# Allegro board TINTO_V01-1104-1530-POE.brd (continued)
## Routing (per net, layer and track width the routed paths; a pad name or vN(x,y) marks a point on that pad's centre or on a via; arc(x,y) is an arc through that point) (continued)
N17701702: length 10.5
  TOP w0.381: v1(185.03,12.85) 185.03,11.78 LED38.4 ; v1(190,17.82) 191.11,17.82 LED36.3
  IN1 w0.381: v1(185.03,12.85) v1(190,17.82)
N17701704: length 16
  TOP w0.381: LED21.2 v1(12.14,124.69) ; LED23.1 v1(12.11,110.13)
  IN1 w0.381: v1(12.14,124.69) 12.14,110.17 v1(12.11,110.13)
N17701706: length 15.9
  TOP w0.381: v1(11.5,110.87) 10.97,110.87 10.63,110.53 LED23.3 ; LED21.4 10.63,124.21 10.98,123.86 v1(11.5,123.86)
  IN1 w0.381: v1(11.5,110.87) v1(11.5,123.86)
N17702195: length 10.5
  TOP w0.381: LED37.4 20.5,10.74 20.91,11.15 v1(20.91,11.58) ; v1(27.96,11.58) 27.96,10.83 28.16,10.64 LED39.3
  IN1 w0.381: v1(27.96,11.58) v1(20.91,11.58)
N17702197: length 10.4
  TOP w0.381: LED37.2 v1(19.86,12.24) ; LED39.1 28.67,12.12 v1(28.67,12.13)
  IN1 w0.381: v1(28.67,12.13) 28.55,12.24 v1(19.86,12.24)
N17702222: length 10.3
  TOP w0.381: v1(190.36,20.88) 191.37,19.87 ; LED34.1 v1(190.36,28.65)
  IN1 w0.381: v1(190.36,28.65) v1(190.36,20.88)
N17702224: length 10.3
  TOP w0.381: v1(191,27.78) 191.56,27.78 192.18,28.4 LED34.3 ; LED36.4 192.07,20.18 v1(191,21.25)
  IN1 w0.381: v1(191,21.25) v1(191,27.78)
N17702236: length 16.2
  TOP w0.381: v1(190.62,44.64) 190.63,44.65 LED32.1 ; v1(190.62,30.11) 190.63,30.1 LED34.2
  IN1 w0.381: v1(190.62,30.11) 190.61,30.12 190.61,44.64 v1(190.62,44.64)
N17702240: length 15.9
  TOP w0.381: v1(191.26,43.9) 191.77,43.9 192.18,44.3 LED32.3 ; LED34.4 192.18,30.4 191.78,30.79 v1(191.25,30.79)
  IN1 w0.381: v1(191.25,30.79) 191.25,43.88 v1(191.26,43.9)
N17702242: length 16.2
  TOP w0.381: LED32.2 190.78,46.1 190.55,46.33 v1(190.55,46.35) ; LED30.1 v1(190.53,60.65)
  IN1 w0.381: v1(190.53,60.65) 190.53,46.36 v1(190.55,46.35)
N17702244: length 16
  TOP w0.381: v1(191.17,59.87) 191.66,59.87 192.18,60.39 LED30.3 ; LED32.4 192.18,46.47 191.74,46.91 v1(191.17,46.91)
  IN1 w0.381: v1(191.17,46.91) v1(191.17,59.87)
N17702269: length 16.1
  TOP w0.381: v1(190.68,92.63) 190.69,92.63 LED26.1 ; LED28.2 v1(190.75,78.11)
  IN1 w0.381: v1(190.75,78.11) 190.5,78.35 190.5,92.45 v1(190.68,92.63)
N17702271: length 16.1
  TOP w0.381: v1(191.13,78.83) 191.68,78.83 192.18,78.33 LED28.4 ; v1(191.13,91.86) 191.75,91.86 192.15,92.26 LED26.3
  IN1 w0.381: v1(191.13,78.83) v1(191.13,91.86)
N17702317: length 16.3
  TOP w0.381: LED28.1 190.6,76.66 v1(190.59,76.67) ; v1(190.59,62.09) 190.6,62.1 LED30.2
  IN1 w0.381: v1(190.59,62.09) 190.59,62.09 v1(190.59,76.67)
N17702327: length 15.9
  TOP w0.381: LED30.4 192.18,62.47 191.82,62.83 v1(191.23,62.83) ; LED28.3 192.18,76.38 191.65,75.86 v1(191.23,75.86)
  IN1 w0.381: v1(191.23,62.83) v1(191.23,75.86)
N17702414: length 16.3
  TOP w0.381: v1(60.69,12.38) 60.68,12.37 LED41.1 ; v1(46.54,12.38) 46.13,11.96 LED40.2
  IN1 w0.381: v1(46.54,12.38) v1(60.69,12.38)
N17702416: length 16.1
  TOP w0.381: v1(59.91,11.69) 59.91,11.1 60.37,10.64 LED41.3 ; v1(46.85,11.62) 46.82,11.59 46.82,11.03 46.42,10.64 LED40.4
  IN1 w0.381: v1(59.91,11.69) 46.92,11.69 v1(46.85,11.62)
N17702418: length 16.1
  TOP w0.381: LED41.2 v1(62.13,12.1) ; LED42.1 v1(76.68,12.09)
  IN1 w0.381: v1(62.13,12.1) 62.3,12.27 76.5,12.27 v1(76.68,12.09)
N17702420: length 16
  TOP w0.381: v1(62.98,11.62) 62.98,11.62 62.98,11.21 62.4,10.64 LED41.4 ; v1(75.97,11.63) 75.95,11.61 75.95,11.02 76.33,10.64 LED42.3
  IN1 w0.381: v1(62.98,11.62) 62.99,11.63 v1(75.97,11.63)
N17702422: length 16.2
  TOP w0.381: LED42.2 v1(78.13,12.09) ; LED43.1 v1(92.68,12.09)
  IN1 w0.381: v1(78.13,12.09) 78.42,12.38 92.39,12.38 v1(92.68,12.09)
N17702424: length 16.2
  TOP w0.381: LED43.3 92.41,10.64 92.03,11.01 v1(92.03,11.73) ; v1(78.9,11.73) 78.9,11.14 78.4,10.64 LED42.4
  IN1 w0.381: v1(92.03,11.73) v1(78.9,11.73)
N17702426: length 16.4
  TOP w0.381: v1(110.14,12.32) 110.13,12.31 LED44.2 ; LED45.1 124.69,12.28 v1(124.69,12.29)
  IN1 w0.381: v1(110.14,12.32) 110.18,12.35 124.62,12.35 v1(124.69,12.29)
N17702428: length 16.2
  TOP w0.381: LED45.3 124.33,10.64 123.97,11 v1(123.97,11.69) ; LED44.4 110.45,10.64 110.82,11.01 v1(110.82,11.69)
  IN1 w0.381: v1(123.97,11.69) v1(110.82,11.69)
N17702430: length 16.3
  TOP w0.381: LED44.1 v1(108.68,12.19) ; LED43.2 v1(94.13,12.11)
  IN1 w0.381: v1(94.13,12.11) 94.4,12.38 108.49,12.38 v1(108.68,12.19)
N17702432: length 16.2
  TOP w0.381: LED43.4 94.52,10.64 95.09,11.21 v1(95.09,11.74) ; LED44.3 108.23,10.64 107.88,10.99 v1(107.88,11.74)
  IN1 w0.381: v1(107.88,11.74) v1(95.09,11.74)
N17702434: length 16.3
  TOP w0.381: LED46.1 140.69,12.25 v1(140.66,12.28) ; v1(126.14,12.27) LED45.2
  IN1 w0.381: v1(140.66,12.28) 126.14,12.28 v1(126.14,12.27)
N17702436: length 16
  TOP w0.381: LED45.4 126.42,10.64 126.96,11.18 v1(126.96,11.64) ; LED46.3 140.46,10.64 139.99,11.11 v1(139.99,11.64)
  IN1 w0.381: v1(139.99,11.64) v1(126.96,11.64)
N17702438: length 16
  TOP w0.381: LED47.1 v1(156.69,12.11) ; LED46.2 v1(142.14,12.09)
  IN1 w0.381: v1(156.69,12.11) 156.66,12.14 142.19,12.14 v1(142.14,12.09)
N17702440: length 15.8
  TOP w0.381: LED47.3 156.44,10.64 155.94,11.13 v1(155.94,11.51) ; v1(142.9,11.51) 142.9,11.04 142.49,10.64 LED46.4
  IN1 w0.381: v1(155.94,11.51) v1(142.9,11.51)
N17702495: length 10.2
  TOP w0.381: v1(20.08,190.61) 20.08,191.22 LED11.1 ; LED1.2 v1(28.67,190.61)
  IN1 w0.381: v1(20.08,190.61) v1(28.67,190.61)
N17702497: length 10.2
  TOP w0.381: LED1.4 28.29,192.16 27.94,191.8 v1(27.94,191.26) ; v1(20.79,191.26) 20.79,191.57 20.29,192.08 LED11.3
  IN1 w0.381: v1(27.94,191.26) v1(20.79,191.26)
N17702499: length 9.8
  TOP w0.381: LED11.2 18.57,190 v1(18.28,189.71) ; v1(12.82,184.27) LED13.1
  IN1 w0.381: v1(18.28,189.71) 12.84,184.27 v1(12.82,184.27)
N17702501: length 10.5
  TOP w0.381: LED11.4 17.79,191.04 v1(17.79,190.17) ; v1(12.64,185.02) 11.73,185.02 LED13.3
  IN1 w0.381: v1(12.64,185.02) v1(17.79,190.17)
N17702503: length 9.6
  TOP w0.381: LED13.2 v1(12.14,182.19) ; LED15.1 11.76,174.14 v1(12.11,174.49)
  IN1 w0.381: v1(12.14,182.19) 12.16,182.17 12.16,174.55 v1(12.11,174.49)
N17702505: length 10.2
  TOP w0.381: LED15.3 10.63,174.47 11.1,174.94 v1(11.48,174.94) ; LED13.4 10.72,182.33 11.09,181.96 v1(11.53,181.96)
  IN1 w0.381: v1(11.53,181.96) 11.53,174.99 v1(11.48,174.94)
N17702507: length 16
  TOP w0.381: LED17.2 v1(12.14,156.69) ; LED19.1 v1(12.08,142.14)
  IN1 w0.381: v1(12.14,156.69) 12.14,142.2 v1(12.08,142.14)
N17702509: length 15.8
  TOP w0.381: LED17.4 10.63,156.23 10.9,155.96 v1(11.47,155.96) ; LED19.3 10.63,142.41 11.11,142.89 v1(11.47,142.89)
  IN1 w0.381: v1(11.47,142.89) v1(11.47,155.96)
N17702511: length 16
  TOP w0.381: LED15.2 v1(12.12,172.69) ; LED17.1 v1(12.08,158.14)
  IN1 w0.381: v1(12.12,172.69) 12.11,172.68 12.11,158.17 v1(12.08,158.14)
N17702513: length 15.8
  TOP w0.381: v1(11.48,158.91) 11.08,158.91 10.63,158.46 LED17.3 ; v1(11.48,171.86) 11.02,171.86 10.63,172.24 LED15.4
  IN1 w0.381: v1(11.48,158.91) v1(11.48,171.86)
N17702515: length 16.1
  TOP w0.381: LED21.1 v1(12.1,126.14) ; LED19.2 v1(12.11,140.69)
  IN1 w0.381: v1(12.11,140.69) 12.18,140.62 12.18,126.22 v1(12.1,126.14)
N17702517: length 15.9
  TOP w0.381: v1(11.51,139.98) 10.92,139.98 10.63,140.27 LED19.4 ; LED21.3 10.63,126.53 11.02,126.92 v1(11.51,126.92)
  IN1 w0.381: v1(11.51,126.92) v1(11.51,139.98)
N17702581: length 10.4
  TOP w0.381: LED48.2 v1(174.14,12.29) ; LED38.1 182.68,11.62 v1(182.68,12.3)
  IN1 w0.381: v1(182.68,12.3) 182.67,12.29 v1(174.14,12.29)
N17702583: length 10.5
  TOP w0.381: v1(182.03,11.63) 182.03,11.2 182.51,10.72 183.17,10.72 ; LED48.4 174.49,10.64 175.03,11.18 v1(175.03,11.72)
  IN1 w0.381: v1(175.03,11.72) 175.11,11.63 v1(182.03,11.63)
N17736265: length 16
  TOP w0.381: v1(190.7,110.08) 190.71,110.08 LED24.2 ; LED22.1 v1(190.74,124.64)
  IN1 w0.381: v1(190.74,124.64) 190.68,124.58 190.68,110.11 v1(190.7,110.08)
N17736966: length 15.9
  TOP w0.381: v1(191.31,123.93) 191.91,123.93 192.18,124.2 LED22.3 ; LED24.4 192.18,110.4 191.76,110.82 v1(191.31,110.82)
  IN1 w0.381: v1(191.31,123.93) v1(191.31,110.82)
N17737669: length 16
  TOP w0.381: v1(190.7,126.09) 190.71,126.09 LED22.2 ; LED20.1 v1(190.72,140.64)
  IN1 w0.381: v1(190.72,140.64) 190.67,140.59 190.67,126.13 v1(190.7,126.09)
N17738374: length 15.8
  TOP w0.381: v1(191.3,126.97) 191.55,126.97 192.18,126.34 LED22.4 ; LED20.3 192.18,140.11 191.88,139.81 v1(191.3,139.81)
  IN1 w0.381: v1(191.3,126.97) v1(191.3,139.81)
N17739081: length 16
  TOP w0.381: LED20.2 v1(190.73,142.09) ; LED18.1 v1(190.73,156.67)
  IN1 w0.381: v1(190.73,142.09) 190.68,142.13 190.68,156.63 v1(190.73,156.67)
N17739790: length 15.9
  TOP w0.381: LED20.4 192.18,142.51 191.83,142.87 v1(191.32,142.87) ; LED18.3 192.18,156.15 191.86,155.83 v1(191.32,155.83)
  IN1 w0.381: v1(191.32,155.83) v1(191.32,142.87)
N17740501: length 16.1
  TOP w0.381: LED16.1 v1(190.74,172.64) ; LED18.2 v1(190.75,158.12)
  IN1 w0.381: v1(190.74,172.64) 190.56,172.46 190.56,158.3 v1(190.75,158.12)
N17741214: length 16
  TOP w0.381: v1(191.2,171.92) 191.76,171.92 192.18,172.34 LED16.3 ; v1(191.2,158.97) 191.7,158.97 192.18,158.48 LED18.4
  IN1 w0.381: v1(191.2,171.92) v1(191.2,158.97)
N17741929: length 10.1
  TOP w0.381: LED16.2 190.65,174.09 v1(190.65,174.09) ; LED14.1 191.01,182.88 v1(190.62,182.49)
  IN1 w0.381: v1(190.65,174.09) 190.62,174.11 v1(190.62,182.49)
N17742646: length 10.4
  TOP w0.381: LED14.3 192.08,182.39 191.73,182.05 v1(191.27,182.05) ; LED16.4 192.18,174.57 191.88,174.87 191.27,174.87 v1(191.27,174.87)
  IN1 w0.381: v1(191.27,174.87) v1(191.27,182.05)
N17743365: length 9.8
  TOP w0.381: LED14.2 190.01,184.23 v1(190,184.24) ; LED12.1 v1(184.28,189.92)
  IN1 w0.381: v1(184.28,189.92) 184.31,189.92 v1(190,184.24)
N17744086: length 10.5
  TOP w0.381: LED12.3 184.97,191.1 v1(184.97,190.18) ; v1(190.23,184.94) 191.12,184.94 LED14.4
  IN1 w0.381: v1(190.23,184.94) 184.99,190.18 v1(184.97,190.18)
N17744809: length 9.8
  TOP w0.381: v1(182.15,190.57) 182.15,190.57 LED12.2 ; v1(174.46,190.57) 174.12,190.92 LED10.1
  IN1 w0.381: v1(174.46,190.57) 182.15,190.57 v1(182.15,190.57)
N17745534: length 10.1
  TOP w0.381: v1(174.95,191.24) 174.95,191.85 174.65,192.16 LED10.3 ; LED12.4 182.65,192.04 v1(181.86,191.24)
  IN1 w0.381: v1(181.86,191.24) 174.95,191.24 v1(174.95,191.24)
N17756919: length 16
  TOP w0.381: LED9.2 v1(156.66,190.7) ; LED8.1 142.11,190.72 v1(142.12,190.71)
  IN1 w0.381: v1(156.66,190.7) 156.63,190.66 142.17,190.66 v1(142.12,190.71)
N17756921: length 15.8
  TOP w0.381: LED9.4 156.26,192.16 155.87,191.76 v1(155.87,191.3) ; LED8.3 142.38,192.16 142.85,191.7 v1(142.85,191.3)
  IN1 w0.381: v1(142.85,191.3) v1(155.87,191.3)
N17756923: length 16
  TOP w0.381: v1(126.12,190.71) 126.11,190.72 LED7.1 ; LED8.2 v1(140.66,190.68)
  IN1 w0.381: v1(126.12,190.71) 126.15,190.68 140.66,190.68 v1(140.66,190.68)
N17756925: length 15.7
  TOP w0.381: LED7.3 126.45,192.16 126.82,191.79 v1(126.82,191.32) ; LED8.4 140.34,192.16 139.88,191.7 v1(139.88,191.32)
  IN1 w0.381: v1(126.82,191.32) v1(139.88,191.32)
N17756927: length 15.9
  TOP w0.381: LED6.1 110.13,190.72 v1(110.14,190.71) ; LED7.2 v1(124.66,190.72)
  IN1 w0.381: v1(110.14,190.71) 110.17,190.69 124.63,190.69 v1(124.66,190.72)
N17756929: length 15.8
  TOP w0.381: LED6.3 110.6,192.16 110.91,191.86 v1(110.91,191.32) ; LED7.4 124.29,192.16 123.9,191.77 v1(123.9,191.32)
  IN1 w0.381: v1(110.91,191.32) v1(123.9,191.32)
N17756931: length 16
  TOP w0.381: v1(108.67,190.71) 108.68,190.73 LED6.2 ; LED5.1 v1(94.13,190.71)
  IN1 w0.381: v1(94.13,190.71) 94.16,190.68 108.64,190.68 v1(108.67,190.71)
N17756933: length 15.8
  TOP w0.381: LED6.4 108.31,192.16 107.92,191.76 v1(107.92,191.31) ; LED5.3 94.51,192.16 94.87,191.79 v1(94.87,191.31)
  IN1 w0.381: v1(94.87,191.31) v1(107.92,191.31)
N17756935: length 16
  TOP w0.381: LED5.2 v1(92.68,190.72) ; LED4.1 v1(78.13,190.69)
  IN1 w0.381: v1(78.13,190.69) 92.64,190.69 v1(92.68,190.72)
N17756937: length 15.6
  TOP w0.381: v1(91.93,191.32) 91.93,191.63 92.45,192.16 LED5.4 ; LED4.3 78.4,192.16 78.9,191.65 v1(78.9,191.32)
  IN1 w0.381: v1(91.93,191.32) v1(78.9,191.32)
N17756939: length 16
  TOP w0.381: LED3.1 v1(62.13,190.71) ; LED4.2 v1(76.68,190.73)
  IN1 w0.381: v1(62.13,190.71) 62.21,190.63 76.58,190.63 v1(76.68,190.73)
N17756941: length 15.7
  TOP w0.381: LED3.3 62.39,192.16 62.86,191.69 v1(62.86,191.3) ; LED4.4 76.38,192.16 75.9,191.67 v1(75.9,191.3)
  IN1 w0.381: v1(75.9,191.3) v1(62.86,191.3)
N17756943: length 15.9
  TOP w0.381: v1(46.36,190.68) 46.13,190.92 LED2.1 ; LED3.2 v1(60.68,190.67)
  IN1 w0.381: v1(46.36,190.68) 46.39,190.65 60.66,190.65 v1(60.68,190.67)
N17756945: length 15.8
  TOP w0.381: LED2.3 46.47,192.16 46.89,191.74 v1(46.89,191.29) ; LED3.4 60.31,192.16 59.9,191.75 v1(59.9,191.29)
  IN1 w0.381: v1(46.89,191.29) v1(59.9,191.29)
N25585706: length 19.3
  BOTTOM w0.254: C264.2 C276.2 43.65,134.76 42.3,133.41 42.3,132.47 43.44,131.34 43.69,131.34 U25.4 44.85,127.5 45.98,126.37 48.62,126.37 49.26,127.02 49.26,127.26 R219.1 R216.2
N25585768: length 4.9
  BOTTOM w0.508: T1.1 67.99,144.77 R193.2
N25585770: length 8.9
  BOTTOM w0.254: D12.P 46,132.71 45.73,132.98 U25.3 44.85,133.64 45.53,134.32 C276.1 45.53,135.36 45.45,135.43 R208.1 46.58,136.13 47.33,136.88 U22.2
N25585804: length 30
  TOP w0.381: U4.4 v1(86.85,147.3)
  IN2 w0.508: v1(86.85,147.3) 81.77,147.3 77.58,143.11 77.58,137.52 75.23,135.17 v1(73.01,135.17)
  BOTTOM w0.508: D10.3 69.71,136.03 C275.1 69.74,135.05 70.01,135.05 C278.1 72.88,135.05 v1(73.01,135.17)
N25586716: length 14.9
  BOTTOM w0.254: R216.1 50.51,132.01 49.81,132.71 D12.N 48.92,127.89 48.01,126.98 R236.1 ; R217.2 51.78,132.04 49.26,134.55 R213.1
  BOTTOM w0.508: R216.1 R217.2
N25586736: length 4.8
  BOTTOM w0.508: R193.1 71.55,142.24 71.08,141.77 C259.1 71.08,140.65 D10.1
N25586772: length 2.6
  TOP w0.305: R48.1 88.88,141.59 88.15,142.32 U4.13
N25586778: length 2.7
  TOP w0.305: U4.14 88.9,142.2 89.87,141.23 R49.1
N25586811: length 1.8
  BOTTOM w0.508: U22.1 R213.2
N25586821: length 4.1
  TOP w0.381: U4.3 87.5,151.38 R11.2
N25586908: length 23.5
  TOP w0.508: Q1.4 62.82,155.05 83.91,155.05 R16.2
N25586910: length 25.2
  TOP w0.508: R11.1 v1(85.84,155.56)
  IN1 w0.508: v1(85.84,155.56) 83.42,153.15 65.01,153.15 v1(63.36,151.49)
N25587094: length 3
  TOP w0.305: U4.10 86.2,142.46 84.95,141.21 R54.2
N25587194: length 1.4
  BOTTOM w0.254: R208.2 C264.1
N25587240: length 4.7
  BOTTOM w0.254: C283.1 46.54,129.99 47.26,130.71 D12.NP
  BOTTOM w0.508: R236.2 C283.1
N25587378: length 2.6
  TOP w0.305: U4.11 86.85,142.27 86.34,141.77 R55.2
N25587545: length 4.2
  TOP w0.381: U4.5 86.2,151.28 R16.1
N25594365: length 13.9
  TOP w0.102: CN3.5 80.26,111.19 CN3.6 83.73,114.66 88.02,114.66 C153.2
N25594481: length 12.7
  TOP w0.102: CN3.12 81.64,117.2 82.91,118.47 87.36,118.47 89.14,120.25 R97.1
N25594574: length 6.4
  TOP w0.102: R98.1 88.88,119.24 87.87,118.22 84.84,118.22 CN3.13
N25594579: length 5.8
  TOP w0.102: R99.1 91.4,119.08 89.52,117.2 CN3.14
N26013479: length 1.4
  TOP w0.381: R10.1 88.66,155.29 88.63,155.27 C28.2

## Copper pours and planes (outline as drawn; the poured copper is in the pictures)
3VDDM on BOTTOM (solid shape): 142.99,166.99 142.99,165.48 142.78,165.28 142.51,165.28 142.22,165.22 141.97,165.05 141.93,165.02 139.26,165.02 138.44,164.19 137.14,164.19 136.93,164.41 136.93,166.01 137.27,166.35 137.65,166.35 137.91,166.61 137.91,167.24 138.03,167.37 142.6,167.37
5V_SW on BOTTOM (solid shape): 36,119.45 36,118.12 38.32,115.8 38.32,110.67 37.5,109.85 33.86,109.85 33.51,110.2 33.51,114.46 34.35,115.3 34.35,116.91 34.95,117.51 34.95,119.57 35.13,119.75 35.7,119.75
5VDDM on BOTTOM (solid shape): 37.38,90.02 37.38,87.52 36.46,86.6 33.98,86.6 33.17,87.41 33.17,90.12 33.62,90.57 36.83,90.57
5VDDM on BOTTOM (solid shape): 120.89,94.22 120.89,92.82 120.63,92.57 118.86,92.57 118.47,92.95 118.47,94.47 118.73,94.73 120.38,94.73
5VDDM on BOTTOM (solid shape): 143.68,44.85 143.68,42.9 143.47,42.7 140.67,42.7 140.61,42.76 140.61,44.74 141.16,45.29 143.23,45.29
5VDDM on BOTTOM (solid shape): 112.18,92.26 112.18,90.32 112.16,90.29 112.16,89.68 112.02,89.54 110.5,89.54 110.37,89.67 110.37,92.21 110.48,92.32 112.13,92.32
5VDDM on BOTTOM (solid shape): 98.36,179.39 98.43,179.33 98.69,179.08 99.7,179.08 100.21,178.57 100.21,175.9 100.08,175.78 97.67,175.78 96.91,176.54 96.91,179.2 97.16,179.46 98.31,179.46
5VDDM on BOTTOM (solid shape): 170.12,72.33 170.12,71.22 170.12,71.21 170.12,68.3 170.39,68.03 170.39,67.82 170.39,67.82 170.39,67.3 170.38,67.3 170.38,67.11 169.77,66.5 169.77,65.59 169.57,65.39 167.99,65.39 167.76,65.62 167.76,69.47 168.11,69.83 168.11,69.99 168.11,70 168.13,70.11 168.11,70.22 168.11,70.23 168.11,70.46 167.79,70.78 166.09,70.78 165.89,70.58 165.89,68.85 165.81,68.59 165.89,68.33 165.89,67.65 165.81,67.57 165.81,67.01 165.2,66.39 165.2,65.57 164.9,65.28 163.44,65.28 162.91,65.81 162.91,71.42 164.31,72.83 169.63,72.83
5VDDM on VCC2 (solid shape): outline of 638 points within 29.19,42.91 171.94,192.29
5VDDM_VIN on BOTTOM (solid shape): 32.75,119.74 33,119.74 33.26,119.49 33.26,118.09 29.32,114.16 27.29,114.16 26.78,114.66 26.78,120.47 27.07,120.76 31.73,120.76
DVDDL_RGMII on BOTTOM (solid shape): 109.28,121.33 109.28,120.26 109.3,120.13 109.35,120.01 109.36,120 109.36,119.8 108.75,119.19 108.75,118.4 109.2,117.95 109.2,116.34 109.51,116.03 109.51,114.88 108.31,113.69 107.14,113.69 107.04,113.78 107.04,116.13 107.18,116.26 107.58,116.45 107.64,116.9 107.76,117.21 107.6,117.61 107.63,117.69 107.76,118.04 107.59,118.37 107.54,118.45 107.57,118.55 107.66,118.94 107.41,119.25 107.41,119.39 107.4,119.4 107.4,119.57 107.65,119.82 108.46,119.82 108.8,120.16 108.8,121.29 108.89,121.38 109.23,121.38
GND on TOP (solid shape): 11.02,155.41 11.02,143.4 11,143.38 10.53,143.38 10.51,143.4 10.51,155.4 10.55,155.44 10.98,155.44
GND on TOP (solid shape): 11.02,75.33 11.02,63.54 11,63.52 10.53,63.52 10.51,63.54 10.51,75.32 10.55,75.36 10.98,75.36
GND on TOP (solid shape): 11.02,59.23 11.02,47.62 10.98,47.58 10.54,47.58 10.51,47.62 10.51,59.24 10.54,59.27 10.98,59.27
GND on TOP (solid shape): 52.05,139.43 52.05,137.14 51.42,136.51 47.61,136.51 47.23,136.89 47.23,139.43 47.74,139.94 51.55,139.94
GND on TOP (solid shape): 11.02,171.33 11.02,159.43 11,159.41 10.52,159.41 10.51,159.43 10.51,171.35 10.52,171.36 10.98,171.36
GND on TOP (solid shape): 11.02,139.45 11.02,127.46 10.98,127.43 10.54,127.43 10.51,127.47 10.51,139.47 10.52,139.49 10.98,139.49
GND on TOP (solid shape): 11.02,123.33 11.02,111.39 10.99,111.36 10.53,111.36 10.51,111.38 10.51,123.34 10.53,123.36 10.98,123.36
GND on TOP (solid shape): 11.02,107.5 11.02,95.64 10.99,95.61 10.54,95.61 10.51,95.65 10.51,107.51 10.53,107.54 10.98,107.54
GND on TOP (solid shape): 11.02,91.37 11.02,79.51 10.86,79.36 10.57,79.36 10.51,79.42 10.51,91.37 10.53,91.39 10.99,91.39
GND on TOP (solid shape): 192.29,155.32 192.29,143.39 192.27,143.36 191.82,143.36 191.78,143.4 191.78,155.28 191.84,155.33 192.27,155.33
GND on TOP (solid shape): 192.29,139.3 192.29,127.29 192.25,127.25 191.97,127.25 191.78,127.43 191.78,139.27 191.84,139.32 192.28,139.32
GND on TOP (solid shape): 192.29,171.4 192.29,159.38 192.27,159.36 192.01,159.36 191.9,159.46 191.83,159.46 191.78,159.51 191.78,171.39 191.82,171.43 192.26,171.43
GND on TOP (solid shape): 192.29,123.4 192.29,111.27 192.26,111.24 192.05,111.24 191.97,111.32 191.83,111.32 191.78,111.36 191.78,123.38 191.84,123.43 192.26,123.43
GND on TOP (solid shape): outline of 183 points within 24.62,101.33 40.24,129.27
GND on TOP (solid shape): outline of 478 points within 41.51,92.31 71.99,130.67
GND on TOP (solid shape): outline of 136 points within 10.51,175.45 44.62,192.29
GND on BOTTOM (solid shape): 27.11,50.16 27.11,48.06 27.06,48.01 24.98,48.01 24.94,48.05 24.94,50.45 25,50.51 26.76,50.51
GND on BOTTOM (solid shape): 105.37,122.18 105.37,118.72 105.2,118.55 101.5,118.55 101.31,118.74 101.31,122.19 101.52,122.4 105.15,122.4
GND on BOTTOM (solid shape): 122.82,112.36 122.82,111.16 122.7,111.05 120.75,111.05 120.63,111.16 120.63,112.29 120.8,112.46 122.72,112.46
GND on BOTTOM (solid shape): 114.51,162.94 114.51,161.5 114.44,161.43 111.22,161.43 111.22,162.8 111.55,163.13 114.33,163.13
GND on BOTTOM (solid shape): 32.06,47.71 32.06,46.92 31.89,46.75 30.62,46.75 30.44,46.92 30.44,47.58 30.67,47.82 30.99,47.82 31,47.84 31.94,47.84
GND on BOTTOM (solid shape): 43.04,172.7 43.04,169.54 42.97,169.48 41.69,169.48 41.64,169.53 41.64,170.8 40.81,171.62 40.81,172.56 41.05,172.79 42.95,172.79
GND on BOTTOM (solid shape): 52.43,185.02 52.43,183.37 52.31,183.24 51.55,183.24 51.42,183.37 51.42,185.02 51.55,185.15 52.31,185.15
GND on BOTTOM (solid shape): 98.93,78.9 98.93,78.37 99.45,77.85 99.45,76.02 99.21,75.78 96.84,75.78 96.61,76 96.61,79.17 96.8,79.35 98.47,79.35
GND on BOTTOM (solid shape): 104.6,78.71 104.6,77.57 104.5,77.47 102.81,77.47 102.67,77.62 102.67,78.68 102.78,78.79 104.52,78.79
GND on BOTTOM (solid shape): 108.37,160.88 108.37,159.15 108.25,159.02 104.89,159.02 104.77,159.15 104.77,162.19 105.01,162.43 106.82,162.43
GND on BOTTOM (solid shape): 129.8,167.06 129.8,166.38 129.7,166.28 129.29,166.28 128.86,165.84 125.15,165.84 124.94,166.06 124.94,167.28 125.03,167.37 129.5,167.37
GND on BOTTOM (solid shape): 131.88,163.96 132.75,163.96 132.98,163.74 132.98,162.95 132.77,162.75 130,162.75 129.83,162.92 129.83,163.71 130.11,163.99 131.85,163.99
GND on BOTTOM (solid shape): 145.02,160.77 145.02,158.71 144.81,158.5 139.4,158.5 139.23,158.68 139.23,160.92 139.39,161.08 144.7,161.08
GND on BOTTOM (solid shape): 61.07,172.57 61.07,169.53 60.94,169.4 59.93,169.4 59.67,169.66 59.67,170.67 59.17,171.18 58.66,171.18 58.4,171.43 58.4,173.18 58.68,173.46 60.18,173.46
GND on BOTTOM (solid shape): 62.98,184.13 62.98,180.59 62.72,180.34 61.83,180.34 61.32,180.85 61.32,182.99 61.71,183.37 61.71,184.13 61.83,184.26 62.85,184.26
GND on BOTTOM (solid shape): 111.01,133.84 111.01,132.98 111.39,132.6 111.39,132.06 111.26,131.94 110.98,131.94 110.65,132.27 110.19,132.27 109.86,132.6 109.86,133.69 110.27,134.1 110.75,134.1
GND on BOTTOM (solid shape): 114.66,167.24 114.66,163.94 114.62,163.89 112.84,163.89 112.63,164.1 112.63,167.15 112.8,167.33 114.58,167.33
GND on BOTTOM (solid shape): 126.33,111.51 127.53,111.51 127.67,111.37 127.67,110.96 127.54,110.83 124.5,110.83 124.33,111.01 124.33,111.55 124.47,111.69 124.99,111.69 125,111.7 126.15,111.7
GND on BOTTOM (solid shape): 137.65,167.32 137.65,166.73 137.52,166.61 137.22,166.61 136.92,166.3 136.53,166.3 136.46,166.38 136.46,167.32 136.53,167.4 137.58,167.4
GND on BOTTOM (solid shape): 71.1,126.98 71.1,114.92 70.6,114.41 68.06,114.41 67.55,114.92 67.55,120.51 68.94,121.9 68.94,126.98 69.07,127.11 70.98,127.11
GND on BOTTOM (solid shape): 119.53,112.12 119.53,111.67 119.37,111.5 119.37,110.91 119.22,110.76 118.22,110.76 118.01,110.97 116.82,110.97 116.78,111.01 116.78,112.04 117.04,112.3 119.35,112.3
GND on BOTTOM (solid shape): 44.69,184.01 44.69,183.23 44.94,182.99 44.94,182.98 45.07,182.84 45.07,180.74 44.94,180.62 43.51,180.62 43.42,180.7 43.42,182.85 43.42,182.86 43.42,184.01 43.67,184.26 44.43,184.26
GND on BOTTOM (solid shape): 96.6,69.55 96.6,68.84 96.71,68.72 97.12,68.72 97.35,68.5 97.35,67 97.3,66.95 96.75,66.95 96.15,67.55 95.4,67.55 95.29,67.66 95.29,69.51 95.43,69.65 96.5,69.65
GND on BOTTOM (solid shape): 105.14,48.88 105.14,35.29 104.12,34.27 103.17,34.27 103.12,34.33 100.14,34.33 98.97,35.5 98.97,45.28 98.92,45.33 98.92,46.21 97.01,48.12 97.01,49.01 97.39,49.39 104.63,49.39
GND on BOTTOM (solid shape): 121.97,146.27 122.1,146.27 123,145.37 123,144.86 122.93,144.79 120.78,144.79 120.73,144.84 120.73,145.25 120.73,145.25 120.73,146.11 120.73,146.11 120.89,146.27 121.97,146.27
GND on BOTTOM (solid shape): 135.09,112.87 135.55,112.87 135.65,112.77 135.65,111.86 135.49,111.7 133.66,111.7 133.63,111.73 133.6,111.75 133.6,112.7 133.78,112.88 134.2,112.88 134.33,113 134.95,113
GND on BOTTOM (solid shape): 103.74,113.5 103.74,112.38 103.59,112.22 102.63,112.22 102.35,111.94 102.35,110.98 102.22,110.85 99.93,110.85 99.68,111.11 99.68,112.25 99.81,112.38 101.69,112.38 101.81,112.51 101.81,113.12 102.26,113.56 103.68,113.56
GND on BOTTOM (solid shape): 22.93,50.11 22.93,49.67 22.86,49.61 22.44,49.61 22.36,49.53 22.36,48.78 22.26,48.68 21.48,48.68 21.36,48.8 21.36,49.16 21.43,49.24 21.55,49.24 21.6,49.29 21.6,49.76 21.99,50.15 22.89,50.15
GND on BOTTOM (solid shape): 103.04,33.48 103.04,31.56 103.28,31.32 103.93,31.32 104.04,31.21 104.04,30.67 103.93,30.56 103.29,30.56 102.97,30.23 102.97,28.8 102.73,28.56 100.69,28.56 100.49,28.76 100.49,33.6 100.63,33.73 102.79,33.73
GND on BOTTOM (solid shape): 146.28,123.94 146.29,123.93 146.38,123.8 146.51,123.71 146.53,123.69 146.53,122.07 146.34,121.88 144.94,121.88 144.63,122.19 144.63,122.9 144.61,122.91 144.61,123.43 144.84,123.66 144.91,123.66 145.29,124.04 146.18,124.04
GND on BOTTOM (solid shape): 66.66,112.76 66.66,106.54 64.63,104.5 64.63,97.39 64.12,96.88 53.7,96.88 53.07,97.52 53.07,110.22 53.32,110.47 54.85,110.47 55.36,109.97 55.36,102.09 56.88,100.57 61.07,100.57 62.34,101.84 62.34,108.06 62.47,108.19 64.12,108.19 64.5,108.57 64.5,113.01 64.75,113.27 66.15,113.27
GND on BOTTOM (solid shape): 100.02,127.99 100.13,127.98 100.25,127.99 100.26,127.99 102.13,127.99 102.33,127.79 102.33,127.66 102.36,127.64 102.36,127.43 102.46,127.43 102.46,126.84 102.37,126.75 99.17,126.75 99.11,126.81 99.11,127.37 99.09,127.37 99.09,127.86 99.23,127.99 100.01,127.99
GND on BOTTOM (solid shape): 159.34,152.31 159.34,151.06 158.96,150.68 157.98,150.68 157.98,150.68 156.85,150.68 156.22,151.32 155.01,151.32 154.95,151.31 154.39,150.75 153.81,150.75 153.81,150.75 151.69,150.75 151.59,150.66 147.56,150.66 147.4,150.81 147.4,152.74 147.68,153.02 158.63,153.02
GND on BOTTOM (solid shape): 54.72,126.09 54.72,123.94 54.47,123.68 53.32,123.68 52.18,122.54 49.89,122.54 45.32,117.97 45.32,110.6 44.56,109.84 42.91,109.84 42.66,109.58 42.66,107.3 42.53,107.17 41.64,107.17 41.39,107.43 41.39,122.03 44.56,125.21 50.53,125.21 52.31,126.98 53.83,126.98
GND on BOTTOM (solid shape): 113.34,83.83 113.34,81.96 113.56,81.74 114.54,81.74 114.64,81.64 114.64,80.75 114.53,80.64 113.45,80.64 113.34,80.52 113.34,79.25 112.89,78.81 109.86,78.81 109.06,79.61 109.06,81.8 108.97,81.89 107.82,81.89 107.75,81.97 107.75,82.25 107.87,82.37 108.91,82.37 109.06,82.52 109.06,83.95 109.57,84.46 112.7,84.46
GND on BOTTOM (solid shape): 33.35,123.08 33.37,123.1 37.31,123.1 37.91,122.49 37.91,119 37.21,118.3 36.6,118.3 36.31,118.59 36.31,119.97 36.04,120.24 32.56,120.24 31.79,121.01 27.03,121.01 26.53,120.51 26.53,115.93 26.4,115.81 24.88,115.81 24.37,116.32 24.37,122.16 25.64,123.43 33,123.43
GND on BOTTOM (solid shape): 106.75,127.95 106.75,127.73 106.68,127.67 106.28,127.67 105.98,127.37 105.59,127.37 105.54,127.32 105.54,126.85 105.46,126.77 103.81,126.77 103.74,126.7 103.3,126.7 103.28,126.72 103.28,127.18 103.34,127.24 103.57,127.24 103.66,127.33 103.75,127.33 103.75,127.34 103.82,127.4 104.38,127.4 104.69,127.71 104.69,127.98 105.08,128.37 106.32,128.37
GND on BOTTOM (solid shape): 118.24,94.11 118.24,92.53 115.89,92.53 115.45,92.97 115.45,93.35 115.32,93.48 114.49,93.48 114.04,93.03 113.46,93.03 113.27,92.83 113.27,91.37 113.34,91.3 113.34,91.25 113.85,90.74 113.85,89.62 113.72,89.49 112.45,89.49 112.36,89.58 112.36,90.21 112.39,90.23 112.39,92.34 112.36,92.37 112.36,94.58 112.53,94.75 117.61,94.75
GND on BOTTOM (solid shape): 130.18,122.03 130.27,121.99 130.31,121.9 130.31,120.29 129.76,119.74 129.76,119.51 129.69,119.39 129.55,119.42 129.51,119.46 129.51,121.46 130.09,122.04
GND on BOTTOM (solid shape): 142.73,154.16 142.73,152 142.49,151.76 142.11,151.76 141.74,152.05 141.31,151.87 140.33,151.87 139.68,152.51 139.68,153.53 140.5,154.34 142.55,154.34
GND on BOTTOM (solid shape): 111.59,154.44 111.59,153.78 111.48,153.67 106.92,153.67 106.72,153.87 106.72,154.67 106.78,154.77 106.9,154.78 107.24,154.78 107.5,155.01 111.02,155.01
GND on BOTTOM (solid shape): 57.72,178.46 57.72,177.85 57.87,177.7 58.53,177.7 58.66,177.57 58.66,175.92 58.94,175.64 59.63,175.64 59.9,175.37 59.9,175.02 59.68,174.79 58.6,174.79 58.56,174.84 58.47,174.91 58.37,174.95 58.37,175.52 57.98,175.92 56.88,175.92 56.81,175.99 56.81,177.52 56.96,177.67 57.11,177.67 57.34,177.9 57.34,178.48 57.4,178.55 57.63,178.55
GND on BOTTOM (solid shape): 39.59,178.51 39.59,177.75 39.75,177.58 40.56,177.58 40.63,177.52 40.63,175.92 40.93,175.61 41.54,175.61 41.98,175.18 41.98,174.98 41.87,174.88 40.45,174.88 40.3,175.03 40.3,175.54 39.94,175.89 38.88,175.89 38.8,175.97 38.8,177.54 38.84,177.58 39.21,177.58 39.33,177.71 39.33,178.09 39.34,178.1 39.36,178.23 39.34,178.36 39.33,178.37 39.33,178.51 39.38,178.56 39.54,178.56
GND on BOTTOM (solid shape): 130.32,112.91 130.71,112.91 130.72,112.9 131.24,112.9 131.32,112.81 131.32,112.42 130.89,111.99 130.74,111.83 130.68,111.63 130.68,111.6 130.53,111.46 129.34,111.46 129.26,111.49 129.18,111.51 128.96,111.73 128.96,112.21 129.25,112.5 129.25,112.79 129.33,112.87 129.45,112.87 129.46,112.87 129.91,112.87 130.05,113.02 130.2,113.02
GND on BOTTOM (solid shape): 100.16,116.12 100.2,116.12 100.4,116.12 100.4,115.51 99.74,114.84 99.24,114.84 99.12,114.92 99.14,115.05 99.22,115.18 99.25,115.31 99.26,115.37 99.47,115.37 99.98,115.87 99.98,116 100.02,116.1 100.13,116.13
GND on BOTTOM (solid shape): 115.81,135.81 115.81,135.6 115.59,135.37 115.57,135.37 115.35,135.19 115.31,134.91 115.31,134.87 115.17,134.73 114.79,134.73 114.28,134.73 114.19,134.82 114.21,134.86 114.23,135.08 114.14,135.28 114.13,135.3 114.13,135.34 114.03,135.44 114.03,135.9 114.06,135.92 115.66,135.92 115.68,135.95
GND on BOTTOM (solid shape): 116.92,122.53 118.37,122.53 118.37,122.3 118.17,122.11 117.35,122.11 117.34,122.15 116.91,122.38 116.6,122 116.56,121.91 116.47,121.88 115.98,121.88 115.64,122.21 112.7,122.21 112.61,122.31 112.61,122.68 112.73,122.81 116.65,122.81
GND on BOTTOM (solid shape): 121.06,117.37 123.41,117.37 123.57,117.21 123.57,116.41 123.19,116.03 123.08,116 122.99,116.08 122.77,116.32 122.45,116.36 122.42,116.36 122.3,116.48 122.08,116.48 122.07,116.48 121.91,116.51 121.75,116.48 121.74,116.48 121.16,116.48 121.12,116.43 117.97,116.43 117.97,117.34 118,117.37 121.06,117.37
GND on BOTTOM (solid shape): 145.7,140.95 145.79,140.98 145.89,140.95 146.18,140.82 146.58,140.96 146.67,140.93 146.72,140.88 146.78,140.84 146.82,140.82 146.82,140.6 145.4,139.17 145.4,136.3 145.14,136.05 145.14,135.9 144.18,134.93 143.8,134.93 143.62,135.11 143.62,138.23 143.06,138.79 143.06,139.58 144.03,140.55 145.3,140.55
GND on BOTTOM (solid shape): 150.78,141.69 150.78,141.59 150.56,141.21 150.78,140.83 150.78,140.7 150.71,140.62 149.64,140.62 148.95,141.31 148.13,141.31 148,141.44 148,141.63 148.14,141.76 149.27,141.76 149.47,141.57 149.48,141.55 149.8,141.32 150.08,141.6 150.08,141.62 150.24,141.78 150.69,141.78
GND on BOTTOM (solid shape): 120.37,161.4 120.37,160.7 120.92,160.15 121.31,160.15 121.45,160.02 121.45,159.78 121.51,159.71 121.51,159.69 121.59,159.52 121.76,159.44 121.78,159.44 122.95,158.28 125.37,158.28 125.42,158.22 126.63,158.22 126.85,158 126.86,158 127.19,157.67 127.19,157.61 127.18,157.59 127.06,157.34 127.11,157.07 127.12,157.05 127.12,157.01 127.19,156.94 127.19,156.05 127.11,155.79 127.19,155.52 127.19,154.25 126.75,153.81 122.4,153.81 122.37,153.85 122.32,153.89 122.22,153.95 122.09,153.98 122.07,153.98 121.87,154.18 121.87,156.57 121.52,156.93 121.52,158.62 121.05,159.1 121.04,159.09 120.39,159.09 120.36,159.09 120.24,159.21 120.24,159.43 120.23,159.44 120.23,159.6 119.8,160.04 119.49,160.04 119.36,160.16 119.36,162.04 119.49,162.16 119.61,162.16
GND on BOTTOM (solid shape): 128.02,158.01 128.06,158.03 128.11,158.01 128.19,157.96 128.29,157.94 128.31,157.94 128.32,157.93 128.4,157.9 128.49,157.89 129.02,157.89 129.14,158.01 129.41,158.01 129.61,157.81 129.67,157.81 129.67,157.79 129.77,157.79 129.78,157.77 129.91,157.71 130.06,157.68 130.47,157.68 130.59,157.61 130.56,157.47 130.2,157.11 129.84,157.11 129.75,157.14 129.71,157.23 129.4,157.63 128.91,157.5 128.89,157.47 128.8,157.47 128.74,157.49 128.69,157.5 128.29,157.5 128.2,157.48 128.12,157.44 128.01,157.42 127.93,157.49 127.84,157.61 127.71,157.7 127.68,157.71 127.68,157.82 127.83,157.82
GND on BOTTOM (solid shape): 112.22,119.8 112.22,119.04 112.25,119.01 112.25,118.12 112.27,118 112.32,117.9 112.32,117.67 112.74,117.25 112.91,117.25 112.92,117.25 113.73,117.25 113.9,117.08 113.9,115.13 113.78,115 110.39,115 109.9,115.49 109.9,116.24 109.4,116.74 109.4,117.64 109.47,117.67 109.52,117.65 109.56,117.61 110,117.51 110.31,117.85 110.09,118.35 109.55,118.29 109.47,118.26 109.38,118.29 109.24,118.38 109.08,118.41 108.99,118.44 108.95,118.53 108.95,118.8 109.77,119.63 109.89,119.66 109.98,119.58 110.01,119.51 110.04,119.46 110.62,119.31 110.86,119.85 110.85,119.86 110.85,120.25 111,120.4 111.62,120.4
GND on BOTTOM (solid shape): 148.06,148.04 148.17,148.07 148.29,148.04 148.35,148.01 148.97,148.01 148.97,147.95 149.02,147.76 149.15,147.61 149.15,146.69 149.47,146.37 149.48,146.35 149.56,146.2 149.72,146.13 149.75,146.1 149.77,146.06 149.77,145.99 149.75,145.95 149.72,145.93 149.55,145.84 149.47,145.67 149.43,145.6 149.35,145.56 149.35,145.56 149.3,145.58 149.28,145.63 149.01,145.93 148.68,145.7 148.67,145.68 148.62,145.62 148.54,145.63 148.5,145.64 148.47,145.68 148.4,145.83 148.25,145.92 148.22,145.95 148.21,145.99 148.21,146.01 148.22,146.05 148.26,146.07 148.34,146.1 148.41,146.15 148.54,146.21 148.73,146.4 148.73,146.75 148.48,147 148.25,147 148.23,147.02 148.14,147.04 148.06,147.08 147.98,147.19 147.96,147.21 147.96,147.66 147.92,147.82 147.98,148
GND on BOTTOM (solid shape): outline of 184 points within 70.21,159.12 99.81,176.26
GND on BOTTOM (solid shape): 130.66,134.24 130.67,134.23 130.78,134.09 130.95,134.03 130.99,134.01 131.01,133.96 131.04,133.79 131.15,133.65 131.2,133.55 131.15,133.45 131,133.15 131.13,132.85 131.18,132.75 131.13,132.66 131.03,132.52 130.99,132.35 130.98,132.31 130.94,132.29 130.78,132.23 130.67,132.11 130.67,132.1 130.57,132 130.48,132.08 130.47,132.09 130.12,132.29 129.84,131.99 129.84,131.94 129.76,131.94 129.72,131.95 129.7,131.99 129.64,132.15 129.51,132.26 129.5,132.27 129.32,132.44 129.31,132.45 128.99,132.66 128.65,132.47 128.64,132.47 128.57,132.39 128.44,132.53 128.41,132.53 128.39,132.54 128.32,132.58 128.24,132.6 128.22,132.6 128.16,132.66 128.28,132.79 128.3,132.79 128.48,132.94 128.54,133.17 128.56,133.21 128.6,133.23 128.76,133.29 128.87,133.42 128.88,133.44 128.96,133.52 129.07,133.41 129.08,133.41 129.62,133.34 129.49,133.87 129.48,133.87 129.37,133.98 129.43,134.04 129.5,134.06 130.04,134.06 130.05,134.05 130.29,134.05 130.47,134.21 130.47,134.22 130.58,134.33
GND on BOTTOM (solid shape): outline of 195 points within 147.32,129.93 160.11,137.7
GND on BOTTOM (solid shape): outline of 375 points within 124.47,137.88 126.81,141.31
GND on BOTTOM (solid shape): outline of 364 points within 117.85,135.74 122.49,140.16
GND on BOTTOM (solid shape): outline of 140 points within 135.21,139.3 147.7,147.98
GND on BOTTOM (solid shape): outline of 550 points within 108.57,50.02 132.19,79.74
GND on BOTTOM (solid shape): outline of 1153 points within 132.71,118.31 138.67,127.36
GND on BOTTOM (solid shape): outline of 10398 points within 10.51,10.51 192.29,192.29
GND on GND1 (solid shape): outline of 1219 points within 10.51,10.51 192.29,192.29
GND on IN1 (solid shape): 96.75,104.13 96.75,101.75 96.76,101.75 96.76,101.33 99.81,98.28 99.81,95.49 96.76,92.44 69.83,92.44 69.33,92.95 69.33,93.96 72.25,96.88 88.5,96.88 93.33,101.71 93.33,104.63 93.71,105.01 95.87,105.01
GND on IN1 (solid shape): 40.5,99.81 40.5,92.69 39.78,91.98 33.48,91.98 27.16,98.3 31.82,98.3 31.82,98.24 31.82,98.18 31.84,98.12 31.86,98.06 31.89,98.01 31.93,97.96 31.97,97.92 32.02,97.89 32.07,97.86 32.12,97.83 32.18,97.82 32.24,97.81 32.3,97.81 32.36,97.82 32.42,97.83 32.47,97.86 32.53,97.89 32.57,97.92 32.62,97.96 32.65,98.01 32.68,98.06 32.71,98.12 32.72,98.18 32.73,98.24 32.73,98.3 32.72,98.36 32.71,98.41 32.68,98.47 32.65,98.52 32.62,98.57 32.57,98.61 32.53,98.65 32.47,98.68 32.42,98.7 32.36,98.72 32.3,98.72 32.24,98.72 32.18,98.72 32.12,98.7 32.07,98.68 32.02,98.65 31.97,98.61 31.93,98.57 31.89,98.52 31.86,98.47 31.84,98.41 31.82,98.36 31.82,98.3 27.16,98.3 26.65,98.81 26.65,100.06 27.03,100.44 39.86,100.44
GND on IN1 (solid shape): outline of 292 points within 26.61,100.95 40.75,128.89
GND on IN1 (solid shape): outline of 443 points within 41.13,92.69 71.87,139.18
GND on IN1 (solid shape): outline of 486 points within 10.51,10.51 192.29,192.29
GND on IN1 (solid shape): outline of 619 points within 22.34,49.06 93.74,163.94
GND on VCC1 (solid shape): outline of 1169 points within 10.51,10.51 192.29,192.29
GND on VCC2 (solid shape): outline of 1197 points within 10.51,10.51 192.29,192.29
GND on IN2 (solid shape): outline of 196 points within 24.49,100.95 40.75,128.89
GND on IN2 (solid shape): outline of 480 points within 41.13,92.69 71.87,139.18
GND on GND2 (solid shape): outline of 1217 points within 10.51,10.51 192.29,192.29
VDD5V_IN on BOTTOM (solid shape): 120.91,91.4 120.91,88.27 120.4,87.76 117.11,87.76 117.11,87.77 116.21,87.77 115.45,88.53 115.39,88.6 115.32,88.65 115.2,88.78 114.31,88.78 114.05,89.03 114.05,89.16 114.31,89.42 114.31,90.57 113.55,91.33 113.55,92.25 113.62,92.33 119.99,92.33
VDD12V_POE on BOTTOM (solid shape): 66.02,121.01 66.02,114.66 65.64,114.28 61.45,114.28 60.05,115.68 60.05,120.63 60.69,121.27 65.77,121.27
VDD13_12 on BOTTOM (solid shape): 39.63,167.66 39.63,165.76 39.38,165.5 38.36,165.5 38.23,165.63 38.23,167.66 38.36,167.79 39.5,167.79
VDD13_12 on BOTTOM (solid shape): 46.97,109.08 46.97,105.77 46.47,105.27 43.42,105.27 43.04,105.65 43.04,109.2 43.16,109.33 46.72,109.33
VDD13_12 on BOTTOM (solid shape): 57.66,167.6 57.66,165.63 57.41,165.38 56.48,165.38 56.24,165.61 56.24,167.51 56.48,167.75 57.51,167.75
VDD13_12 on BOTTOM (solid shape): 28.94,113.65 28.94,111.49 28.81,111.36 26.78,111.36 26.65,111.49 26.65,113.52 27.03,113.9 28.69,113.9
VDD13_12 on VCC1 (solid shape): 89.39,173.11 89.39,168.11 89.19,167.9 89.16,167.88 84.21,167.88 82.94,166.61 82.94,166.61 81.92,165.59 53.6,165.59 38.46,150.46 38.46,121.16 41.13,118.5 41.13,118.5 41.28,118.35 46.61,118.35 48.24,116.72 48.24,105.88 47.63,105.27 27.65,105.27 24.62,108.29 24.62,157.87 40.22,173.47 89.03,173.47
VDD_ARM_CAP on VCC2 (solid shape): 129.21,134.78 129.21,130.75 129.06,130.6 124.01,130.6 123.87,130.75 123.87,134.65 124.14,134.92 129.06,134.92
VDD_IO on BOTTOM (solid shape): 42.95,56.99 42.95,56.43 42.81,56.29 41.53,56.29 41.38,56.44 41.38,57.68 41.47,57.77 42.16,57.77
VDD_IO on BOTTOM (solid shape): 42.48,54.92 42.48,53.33 42.94,52.87 42.94,51.28 42.87,51.22 41.42,51.22 41.37,51.26 41.37,54.89 41.47,54.98 42.42,54.98
VDD_IO on BOTTOM (solid shape): 38.94,49.19 38.94,48.66 38.01,47.73 34.41,47.73 34.32,47.82 33.91,47.82 33.75,47.98 33.1,47.98 32.9,48.18 32.9,49.16 32.99,49.25 33.79,49.25 33.99,49.04 33.99,48.83 34.18,48.64 37.27,48.64 37.95,49.32 38.8,49.32
VDDCORE on BOTTOM (solid shape): 106.48,154.85 106.48,153.78 106.45,153.74 106.45,152.38 106.19,152.13 104.18,152.13 103.8,152.51 103.8,154.7 104.1,155 106.33,155
VDDCORE on VCC1 (solid shape): 119.03,144.99 119.13,144.89 125.99,144.89 128.53,142.35 131.07,142.35 131.56,141.87 131.56,135.34 130.67,134.45 130.67,130.77 129.74,129.84 124.35,129.84 124.3,129.86 124.27,129.84 124.01,129.84 123.87,129.98 123.87,132.49 124,132.62 124,133.92 123.25,134.67 117.13,134.67 116.76,134.3 116.76,134.05 116.43,133.71 112.1,133.71 105.9,139.92 105.9,141.82 104.63,143.09 104.63,154.31 105.14,154.82 109.13,154.82
VDDCORE_R on BOTTOM (solid shape): 112.91,158.1 112.91,154.95 112.88,154.91 111.5,154.91 111.06,155.35 107.52,155.35 107.5,155.39 107.08,155.66 106.66,155.39 106.65,155.35 104.86,155.35 104.63,155.58 104.63,158.28 104.83,158.48 112.53,158.48
VDDPU on VCC1 (solid shape): 129.02,129.25 129.02,125.99 129.16,125.84 130.67,124.34 130.67,118.62 130.52,118.47 122.01,118.47 121.65,118.83 121.65,126.68 124.38,126.68 124.38,120.56 124.87,120.06 127.57,120.06 128.19,120.68 128.19,125.67 127.56,126.3 127.56,126.94 126.94,127.56 125.25,127.56 124.38,126.68 121.65,126.68 121.65,126.83 121.65,126.84 122.24,127.43 123,127.43 123.75,128.18 123.75,128.56 124.13,128.94 124.13,129.19 124.4,129.46 128.81,129.46
VDDSOC on BOTTOM (solid shape): 111.11,163.94 111.11,163.18 110.75,162.82 110.75,161.3 110.7,161.24 108.6,161.24 107.99,161.85 107.99,163.94 108.12,164.07 110.98,164.07
VDDSOC on VCC2 (solid shape): 112.25,164.09 112.25,131.06 111.23,130.04 111.19,129.98 111.17,129.9 111.17,129.14 111.19,129.07 111.23,129 111.6,128.63 111.67,128.59 111.74,128.57 113.06,128.57 113.51,128.12 113.57,128.08 113.65,128.06 123.43,128.06 123.5,128.08 123.57,128.12 124.07,128.62 124.11,128.69 124.13,128.76 124.13,130.08 124.27,130.22 129.57,130.22 130.27,129.52 130.34,129.48 130.41,129.46 130.72,129.46 130.86,129.32 130.86,126.05 130.78,125.97 129.52,125.97 129.43,125.95 129.34,125.89 128.58,125.13 128.53,125.05 128.51,124.95 128.51,120.49 128.15,120.13 113.66,120.13 113.52,120.27 113.52,121.14 113.5,121.24 113.45,121.32 113.07,121.7 112.98,121.76 112.89,121.78 108.93,121.78 104.89,125.82 104.89,162.56 106.77,164.45 111.89,164.45
VDDSOC_CAP on VCC2 (solid shape): 132.38,134.91 132.38,134.6 132.4,134.53 132.44,134.46 132.69,134.22 132.75,134.18 132.83,134.16 133.13,134.16 133.14,134.14 133.14,130.67 133.16,130.59 133.2,130.53 133.45,130.28 133.51,130.24 133.59,130.22 133.89,130.22 134.03,130.08 134.03,128.25 134.05,128.18 134.09,128.11 134.6,127.6 134.63,127.51 134.68,127.44 137.14,124.97 137.14,120.99 136.15,120 131.92,120 131.68,120.23 131.68,124.44 131.61,124.62 131.44,124.7 131.24,124.9 131.24,129.4 131.22,129.47 131.18,129.54 130.93,129.78 130.87,129.83 130.79,129.84 130.49,129.84 129.59,130.75 129.59,134.78 129.73,134.92 129.9,134.92 129.98,134.94 130.04,134.98 130.11,135.05 132.24,135.05
VDDSOC_R on BOTTOM (solid shape): 116.06,161.15 116.06,159.29 115.79,159.02 109.34,159.02 109.16,159.21 109.16,160.65 109.54,161.02 114.52,161.02 114.78,161.29 115.92,161.29
AUX_3V15 on BOTTOM (solid shape): 121.22,166.71 121.22,163.73 121.07,163.58 116.29,163.58 116.05,163.82 115.51,163.82 115.3,164.03 115.3,167.12 115.47,167.29 120.64,167.29
BT_REG_ON on BOTTOM (solid shape): 27.16,52.72 27.16,52.23 27.12,52.19 25.75,52.19 25.62,52.05 23.09,52.05 22.4,51.37 21.89,51.37 21.75,51.51 21.75,52.38 21.94,52.57 25.4,52.57 25.6,52.77 27.11,52.77
DDR_1V5 on BOTTOM (solid shape): 157.39,126.47 157.39,126.14 157.59,125.94 158.4,125.94 158.76,125.59 158.76,123.43 158.38,123.05 157.62,123.05 157.36,123.13 157.1,123.05 156.61,123.05 156.41,123.12 156.21,123.11 156.17,123.09 155.75,123.52 155.75,125.27 155.18,125.84 155.18,126.3 155.41,126.53 155.74,126.53 155.81,126.45 155.81,126.2 156.01,125.99 156.47,125.99 156.78,126.3 156.78,126.35 156.89,126.43 156.97,126.54 156.99,126.58 157.28,126.58
DDR_1V5 on BOTTOM (solid shape): 156.6,150.48 157.89,150.48 158.17,150.2 158.17,148.42 157.98,148.22 157.98,147.74 157.93,147.65 157.83,147.62 157.77,147.62 157.6,147.62 157.21,147.22 157.12,147.18 157.06,147.13 156.97,147.09 156.88,147.13 156.81,147.18 156.74,147.22 156.73,147.23 156.46,147.5 156.03,147.59 155.78,147.23 155.79,147.13 155.83,147.03 155.83,146.91 155.72,146.85 155.41,146.85 155.4,146.9 155.31,147.09 155.15,147.22 155.14,147.22 154.85,147.5 154.62,147.62 154.37,147.57 154.36,147.56 154.02,147.56 153.68,147.9 153.68,150.34 153.88,150.54 154.47,150.54 154.99,151.06 156.01,151.06
DDR_1V5 on BOTTOM (solid shape): 151.67,126.63 151.67,125.59 151.68,125.58 151.68,125.56 151.72,125.45 151.77,125.36 151.77,123.43 151.44,123.1 148.85,123.1 148.57,122.82 148.57,122.18 148.39,122 147.1,122 146.74,122.36 146.74,123.81 146.31,124.24 146.31,124.75 146.54,124.98 146.67,124.98 147.05,125.36 147.05,126.25 147.26,126.45 147.76,126.45 147.98,126.55 148.1,126.66 148.15,126.66 148.19,126.63 148.96,126.63 148.97,126.64 149.29,126.33 149.29,126.02 149.11,125.84 149.09,125.83 148.91,125.77 148.78,125.64 148.74,125.2 149.09,124.93 149.13,124.92 149.13,123.91 149.64,123.41 150.15,123.41 150.41,123.66 150.48,123.78 150.51,123.92 150.51,124.01 150.6,124.01 150.73,124.03 150.85,124.11 151,124.26 151.08,124.38 151.11,124.52 151.11,124.87 150.94,125.04 150.9,125.13 150.94,125.22 151,125.31 151.04,125.4 151.05,125.42 151.06,125.43 151.06,126.58 151.23,126.75 151.55,126.75
DDR_1V5 on BOTTOM (solid shape): 155.9,140.68 155.91,140.67 156.17,140.52 156.44,140.67 156.44,140.68 156.69,140.93 157.26,140.93 157.42,140.76 157.43,140.75 157.46,140.65 157.52,140.57 157.56,140.53 157.56,140.42 157.7,140.29 157.7,140.27 158.09,139.94 158.52,140.21 158.54,140.25 160.41,140.25 160.95,139.71 160.95,136.97 160.26,136.28 160.18,136.28 160.06,136.16 160.02,136.16 159.79,136.16 159.59,136.05 158,136.05 157.77,136.25 157.46,136.26 157.37,136.22 157.26,136.33 157.26,137.58 157.36,137.68 158.59,137.68 158.61,137.67 158.81,137.62 159.01,137.67 159.02,137.68 159.04,137.68 159.06,137.7 159.13,137.76 159.19,137.83 159.29,137.93 159.35,137.87 159.35,137.86 159.69,137.53 160.14,137.68 160.22,138.15 159.85,138.43 159.83,138.44 159.77,138.49 159.77,138.52 159.64,138.79 159.37,138.92 159.35,138.92 159.29,138.98 158.85,138.98 158.44,139.23 158.03,138.98 157.61,138.98 157.32,139.08 157.04,138.98 156.42,138.98 156.41,138.98 156.26,139.01 156.12,138.98 156.11,138.98 155.78,138.98 155.33,139.43 155.33,141.03 155.36,141.06 155.53,141.06
DDR_1V5 on BOTTOM (solid shape): outline of 118 points within 143.54,131.65 150.21,141.05
DDR_1V5 on BOTTOM (solid shape): outline of 243 points within 142.43,146.27 150.38,154.41
DDR_1V5 on VCC1 (solid shape): 161.02,152.15 161.02,118.58 160.28,117.84 134.2,117.84 132.55,119.49 131.32,119.49 131.17,119.63 131.17,124.55 129.52,126.2 129.52,128.91 131.17,130.56 131.17,134.25 132.06,135.13 132.06,144.91 134.2,147.05 138.52,147.05 142.86,151.39 142.86,153.04 143.98,154.16 159.01,154.16
DDR_1V5_L on BOTTOM (solid shape): 144.86,157.77 144.86,155.3 144.61,155.05 137.14,155.05 136.91,155.28 136.91,157.87 137.04,158 144.64,158
DDR_VREF on VCC2 (solid shape): 149.41,156.9 149.49,156.85 149.59,156.83 157.48,156.83 161.27,153.04 161.27,125.19 157.48,121.4 137.76,121.4 137.65,121.5 137.65,125.08 137.63,125.18 137.58,125.26 135.04,127.8 134.96,127.85 134.87,127.87 134.41,128.33 134.41,130.16 134.4,130.24 134.35,130.3 134.11,130.54 134.04,130.59 133.97,130.6 133.67,130.6 133.52,130.75 133.52,134.22 133.51,134.3 133.46,134.36 133.35,134.48 133.28,134.52 133.21,134.54 132.9,134.54 132.76,134.68 132.76,137.07 133.46,137.77 133.51,137.83 133.52,137.91 133.52,139.26 141.39,147.12 141.44,147.21 141.46,147.3 141.46,150.61 141.44,150.7 141.39,150.79 140.57,151.6 140.57,155.56 140.55,155.66 140.5,155.74 137.96,158.28 137.88,158.33 137.78,158.35 132.04,158.35 131.68,158.71 131.68,160.28 132.17,160.77 137.52,160.77 137.62,160.78 137.71,160.84 138.01,161.15 145.17,161.15
ETH_3V3 on BOTTOM (solid shape): 132.38,119.41 132.38,118.37 132.33,118.33 131.22,118.33 131.12,118.42 131.12,118.69 131.23,118.8 131.48,118.8 131.62,118.94 131.62,119.39 131.72,119.48 132.31,119.48
ETH_3V3 on BOTTOM (solid shape): 138.49,150.68 138.49,148.99 138.4,148.89 137.7,148.89 137.39,148.59 137.39,148.46 137.06,148.12 136.4,148.12 135.16,149.37 135.16,150.91 135.31,151.06 138.11,151.06
ETH_3V3 on BOTTOM (solid shape): 98.16,117.14 98.16,116.64 98.31,116.49 98.31,116.4 98.25,116.25 98.24,116.1 98.24,116.07 98.17,116 97.24,116 96.85,116.39 96.85,117.45 96.93,117.53 97.78,117.53
ETH_3V3 on VCC1 (solid shape): 163.43,153.04 163.43,116.93 162.06,115.55 131.91,115.55 131.17,116.29 131.17,118.84 131.32,118.98 132.34,118.98 133.84,117.48 133.84,117.48 133.99,117.33 160.49,117.33 160.64,117.48 160.64,117.48 161.53,118.37 161.53,152.36 159.22,154.67 143.77,154.67 142.35,153.25 142.35,151.6 138.31,147.56 136.49,147.56 136.38,147.66 136.38,149.36 143.72,156.7 159.77,156.7
ETH_3V3 on VCC2 (solid shape): 130.86,125.38 130.86,124.82 130.87,124.75 130.92,124.69 131.17,124.43 131.17,120.13 131.19,120.03 131.25,119.95 131.63,119.56 131.71,119.51 131.81,119.49 132.34,119.49 132.57,119.26 132.57,116.93 126.37,110.73 99.15,110.73 97.14,112.74 97.14,116.59 98.39,117.84 107.32,117.84 108.64,116.52 108.73,116.46 108.82,116.44 112.25,116.44 112.35,116.46 112.43,116.52 113.45,117.53 113.5,117.62 113.52,117.71 113.52,119.48 113.66,119.62 128.25,119.62 128.35,119.64 128.43,119.69 128.94,120.2 129,120.28 129.02,120.38 129.02,124.85 129.63,125.46 130.78,125.46
GEN_1V8 on BOTTOM (solid shape): 144.64,163.18 144.64,161.91 144.38,161.65 143.87,161.65 143.75,161.78 143.75,163.18 144,163.43 144.38,163.43
GEN_1V8 on BOTTOM (solid shape): 137.14,162.16 137.14,161.15 136.76,160.77 134.93,160.77 134.73,160.97 134.73,162.39 134.86,162.52 136.79,162.52
GEN_1V8 on VCC2 (solid shape): 145.02,164.34 145.02,162.02 144.66,161.65 137.91,161.65 137.81,161.64 137.73,161.58 137.42,161.27 132.06,161.27 131.97,161.26 131.88,161.2 131.25,160.57 131.19,160.48 131.17,160.38 131.17,158.61 131.19,158.51 131.25,158.43 131.76,157.92 131.84,157.86 131.94,157.84 135.22,157.84 135.37,157.7 135.37,151.09 131.5,147.23 131.45,147.15 131.43,147.05 131.43,142.71 131.2,142.48 129.88,142.48 127.49,144.87 127.49,146.16 127.47,146.26 127.42,146.34 127.04,146.72 126.95,146.78 126.86,146.8 124.42,146.8 124.19,147.03 124.19,150.88 125.01,151.7 125.06,151.78 125.08,151.88 125.08,152.53 125.31,152.76 126.35,152.76 126.45,152.78 126.53,152.84 127.04,153.35 127.09,153.43 127.11,153.53 127.11,158.23 127.09,158.32 127.04,158.41 126.22,159.22 126.22,159.9 130.34,164.01 130.39,164.1 130.41,164.19 130.41,165.49 130.65,165.72 143.64,165.72
GEN_3V3 on BOTTOM (solid shape): 95,68.63 95,67.49 94.95,67.44 93.37,67.44 93.29,67.53 93.29,68.52 93.45,68.68 94.94,68.68
GEN_3V3 on BOTTOM (solid shape): 105.04,178.95 105.04,176.03 104.78,175.78 102.37,175.78 102.12,176.03 102.12,179.2 102.37,179.46 104.53,179.46
